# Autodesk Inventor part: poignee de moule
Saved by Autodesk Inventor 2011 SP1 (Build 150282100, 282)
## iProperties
Created: 2010-12
Part Number: poignee de moule
Document SubType Name: Modeling
Designer: eric
Density: 1 g/cm^3
Author: eric
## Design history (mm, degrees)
feature "Base1"
node "Solide1"
node "Corps solides"
node "Corps surfaciques"
